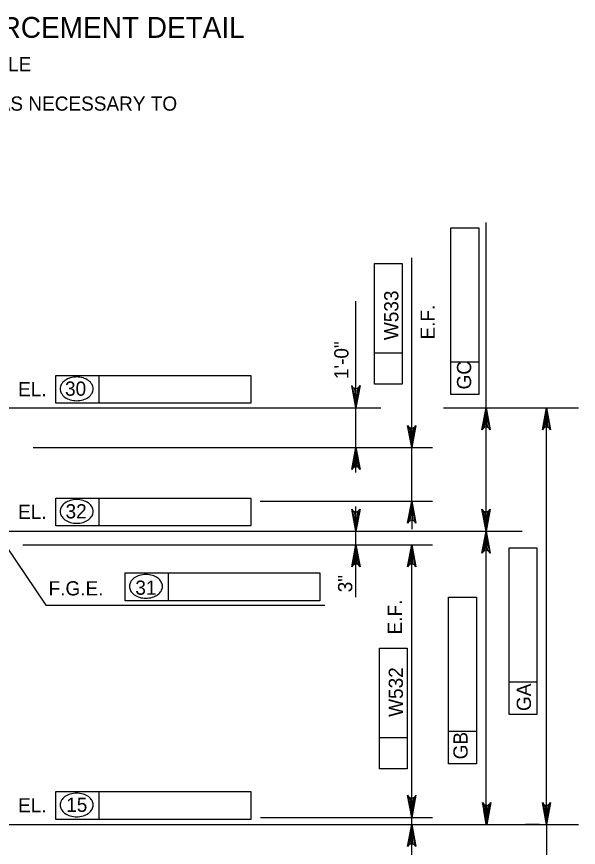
# Model space of a CAD drawing. Extents: x 638255 to 640306, y 296059 to 298435.
# Drawn here: x 638909 to 639027.7, y 296153 to 296328.5 of the extents above; entities that cross this region are included whole.
import ezdxf

# ---------------------------------------------------------------- set-up
doc = ezdxf.new("R2010")
doc.units = 0
doc.layers.add('Level 4', color=7, linetype='Continuous')

msp = doc.modelspace()

# ---------------------------------------------------------------- linework, layer by layer
at = {"layer": 'Level 4'}
for p, q in [((639000.74, 296248.66), (639000.74, 296283.9)), ((639000.74, 296283.9), (639006.63, 296283.9)), ((639006.63, 296283.9), (639006.63, 296248.66)), ((639008.19, 296222.73), (639008.19, 296285.04)), ((638992.48, 296248.08), (638992.48, 296277.54)), ((638984.61, 296250.82), (638984.61, 296276.31)), ((638984.61, 296276.31), (638990.5, 296276.31)), ((638990.5, 296276.31), (638990.5, 296250.82)), ((638980.7, 296232.2), (638980.7, 296268.36)), ((638990.5, 296257.4), (638984.61, 296257.4)), ((639006.63, 296255.5), (639000.74, 296255.5)), ((638917.35, 296252.7), (638958.48, 296252.7)), ((638917.35, 296246.8), (638917.35, 296252.7)), ((638926.5, 296246.8), (638926.5, 296252.7)), ((638958.48, 296252.7), (638958.48, 296246.8)), ((638990.5, 296250.82), (638984.61, 296250.82)), ((638992.48, 296240.42), (638992.48, 296248.08)), ((639006.63, 296248.66), (639000.74, 296248.66)), ((638835.01, 296245.87), (638985.96, 296245.87)), ((638958.48, 296246.8), (638917.35, 296246.8)), ((638999.22, 296245.87), (639027.68, 296245.87)), ((639005.73, 296245.87), (639012.61, 296245.87)), ((639014.63, 296245.87), (639025.37, 296245.87)), ((639020.95, 296157.77), (639020.95, 296245.87)), ((638912.53, 296237.48), (638996.9, 296237.48)), ((638992.48, 296226.13), (638992.48, 296237.48)), ((638917.35, 296226.78), (638958.48, 296226.78)), ((638917.35, 296220.89), (638917.35, 296226.78)), ((638926.5, 296220.89), (638926.5, 296226.78)), ((638958.48, 296226.78), (638958.48, 296220.89)), ((638960.49, 296226.13), (638996.9, 296226.13)), ((638980.7, 296205.86), (638980.7, 296224.96)), ((638992.48, 296223.18), (638992.48, 296220.23)), ((638958.48, 296220.89), (638917.35, 296220.89)), ((638906.78, 296219.78), (639015.83, 296219.78)), ((639002.85, 296219.78), (639012.61, 296219.78)), ((638906.76, 296216.71), (638915.21, 296204.13)), ((638910.35, 296216.92), (638996.9, 296216.92)), ((639008.19, 296160.72), (639008.19, 296216.83)), ((639013.05, 296181.05), (639013.05, 296216.29)), ((639013.05, 296216.29), (639018.94, 296216.29)), ((639018.94, 296216.29), (639018.94, 296181.05)), ((638992.48, 296147.95), (638992.48, 296213.97)), ((638931.98, 296205.06), (638931.98, 296210.96)), ((638931.98, 296210.96), (638973.11, 296210.96)), ((638941.13, 296205.06), (638941.13, 296210.96)), ((638973.11, 296210.96), (638973.11, 296205.06)), ((638973.11, 296205.06), (638931.98, 296205.06)), ((639000.28, 296170.58), (639000.28, 296205.82)), ((639000.28, 296205.82), (639006.18, 296205.82)), ((639006.18, 296205.82), (639006.18, 296170.58)), ((638915.21, 296204.13), (638974.12, 296204.13)), ((638985.66, 296169.55), (638985.66, 296195.04)), ((638985.66, 296195.04), (638991.55, 296195.04)), ((638991.55, 296195.04), (638991.55, 296169.55)), ((639018.94, 296187.89), (639013.05, 296187.89)), ((639018.94, 296181.05), (639013.05, 296181.05)), ((639006.18, 296177.42), (639000.28, 296177.42)), ((638991.55, 296176.13), (638985.66, 296176.13)), ((639006.18, 296170.58), (639000.28, 296170.58)), ((638991.55, 296169.55), (638985.66, 296169.55)), ((638917.35, 296164.76), (638958.48, 296164.76)), ((638917.35, 296158.87), (638917.35, 296164.76)), ((638926.5, 296158.87), (638926.5, 296164.76)), ((638958.48, 296164.76), (638958.48, 296158.87)), ((638960.55, 296159.3), (638996.9, 296159.3)), ((638906.62, 296157.77), (639027.68, 296157.77)), ((638958.48, 296158.87), (638917.35, 296158.87)), ((639002.85, 296157.77), (639012.61, 296157.77)), ((639014.63, 296157.77), (639025.37, 296157.77)), ((639019.48, 296157.77), (639016.53, 296157.77)), ((639020.95, 296157.77), (639020.95, 296145.49))]:
    msp.add_line(p, q, dxfattribs=at)
for points in [[(638980.7, 296245.87), (638979.82, 296250.53), (638980.07, 296250.17), (638980.38, 296249.98), (638980.7, 296249.93), (638981.01, 296249.98), (638981.32, 296250.17), (638981.57, 296250.53), (638980.7, 296245.87), (638981.32, 296250.17), (638981.01, 296249.98), (638980.7, 296245.87), (638980.7, 296249.93), (638980.38, 296249.98), (638980.7, 296245.87), (638980.07, 296250.17)], [(639008.19, 296245.87), (639009.06, 296241.22), (639008.81, 296241.58), (639008.5, 296241.77), (639008.19, 296241.82), (639007.87, 296241.77), (639007.56, 296241.58), (639007.31, 296241.22), (639008.19, 296245.87), (639007.56, 296241.58), (639007.87, 296241.77), (639008.19, 296245.87), (639008.19, 296241.82), (639008.5, 296241.77), (639008.19, 296245.87), (639008.81, 296241.58)], [(639020.95, 296245.87), (639021.82, 296241.22), (639021.57, 296241.58), (639021.26, 296241.77), (639020.95, 296241.82), (639020.63, 296241.77), (639020.32, 296241.58), (639020.07, 296241.22), (639020.95, 296245.87), (639020.32, 296241.58), (639020.63, 296241.77), (639020.95, 296245.87), (639020.95, 296241.82), (639021.26, 296241.77), (639020.95, 296245.87), (639021.57, 296241.58)], [(638992.48, 296237.48), (638991.61, 296242.13), (638991.86, 296241.77), (638992.17, 296241.59), (638992.48, 296241.53), (638992.8, 296241.59), (638993.11, 296241.77), (638993.36, 296242.13), (638992.48, 296237.48), (638993.11, 296241.77), (638992.8, 296241.59), (638992.48, 296237.48), (638992.48, 296241.53), (638992.17, 296241.59), (638992.48, 296237.48), (638991.86, 296241.77)], [(638980.7, 296237.48), (638981.57, 296232.83), (638981.32, 296233.18), (638981.01, 296233.37), (638980.7, 296233.42), (638980.38, 296233.37), (638980.07, 296233.18), (638979.82, 296232.83), (638980.7, 296237.48), (638980.07, 296233.18), (638980.38, 296233.37), (638980.7, 296237.48), (638980.7, 296233.42), (638981.01, 296233.37), (638980.7, 296237.48), (638981.32, 296233.18)], [(638992.48, 296226.13), (638993.36, 296221.48), (638993.11, 296221.83), (638992.8, 296222.02), (638992.48, 296222.07), (638992.17, 296222.02), (638991.86, 296221.83), (638991.61, 296221.48), (638992.48, 296226.13), (638991.86, 296221.83), (638992.17, 296222.02), (638992.48, 296226.13), (638992.48, 296222.07), (638992.8, 296222.02), (638992.48, 296226.13), (638993.11, 296221.83)], [(638980.7, 296219.78), (638979.82, 296224.43), (638980.07, 296224.07), (638980.38, 296223.89), (638980.7, 296223.84), (638981.01, 296223.89), (638981.32, 296224.07), (638981.57, 296224.43), (638980.7, 296219.78), (638981.32, 296224.07), (638981.01, 296223.89), (638980.7, 296219.78), (638980.7, 296223.84), (638980.38, 296223.89), (638980.7, 296219.78), (638980.07, 296224.07)], [(639008.19, 296219.78), (639007.31, 296224.43), (639007.56, 296224.07), (639007.87, 296223.89), (639008.19, 296223.84), (639008.5, 296223.89), (639008.81, 296224.07), (639009.06, 296224.43), (639008.19, 296219.78), (639008.81, 296224.07), (639008.5, 296223.89), (639008.19, 296219.78), (639008.19, 296223.84), (639007.87, 296223.89), (639008.19, 296219.78), (639007.56, 296224.07)], [(639008.19, 296219.78), (639009.06, 296215.13), (639008.81, 296215.49), (639008.5, 296215.67), (639008.19, 296215.73), (639007.87, 296215.67), (639007.56, 296215.49), (639007.31, 296215.13), (639008.19, 296219.78), (639007.56, 296215.49), (639007.87, 296215.67), (639008.19, 296219.78), (639008.19, 296215.73), (639008.5, 296215.67), (639008.19, 296219.78), (639008.81, 296215.49)], [(638980.7, 296216.92), (638981.57, 296212.27), (638981.32, 296212.63), (638981.01, 296212.81), (638980.7, 296212.86), (638980.38, 296212.81), (638980.07, 296212.63), (638979.82, 296212.27), (638980.7, 296216.92), (638980.07, 296212.63), (638980.38, 296212.81), (638980.7, 296216.92), (638980.7, 296212.86), (638981.01, 296212.81), (638980.7, 296216.92), (638981.32, 296212.63)], [(638992.48, 296216.92), (638993.36, 296212.27), (638993.11, 296212.63), (638992.8, 296212.81), (638992.48, 296212.86), (638992.17, 296212.81), (638991.86, 296212.63), (638991.61, 296212.27), (638992.48, 296216.92), (638991.86, 296212.63), (638992.17, 296212.81), (638992.48, 296216.92), (638992.48, 296212.86), (638992.8, 296212.81), (638992.48, 296216.92), (638993.11, 296212.63)], [(638992.48, 296159.3), (638991.61, 296163.96), (638991.86, 296163.6), (638992.17, 296163.41), (638992.48, 296163.36), (638992.8, 296163.41), (638993.11, 296163.6), (638993.36, 296163.96), (638992.48, 296159.3), (638993.11, 296163.6), (638992.8, 296163.41), (638992.48, 296159.3), (638992.48, 296163.36), (638992.17, 296163.41), (638992.48, 296159.3), (638991.86, 296163.6)], [(639008.33, 296157.77), (639007.46, 296162.42), (639007.71, 296162.06), (639008.02, 296161.88), (639008.33, 296161.82), (639008.64, 296161.88), (639008.96, 296162.06), (639009.2, 296162.42), (639008.33, 296157.77), (639008.96, 296162.06), (639008.64, 296161.88), (639008.33, 296157.77), (639008.33, 296161.82), (639008.02, 296161.88), (639008.33, 296157.77), (639007.71, 296162.06)], [(639020.95, 296157.77), (639020.07, 296162.42), (639020.32, 296162.06), (639020.63, 296161.88), (639020.95, 296161.82), (639021.26, 296161.88), (639021.57, 296162.06), (639021.82, 296162.42), (639020.95, 296157.77), (639021.57, 296162.06), (639021.26, 296161.88), (639020.95, 296157.77), (639020.95, 296161.82), (639020.63, 296161.88), (639020.95, 296157.77), (639020.32, 296162.06)], [(638992.48, 296157.77), (638993.36, 296153.12), (638993.11, 296153.47), (638992.8, 296153.66), (638992.48, 296153.71), (638992.17, 296153.66), (638991.86, 296153.47), (638991.61, 296153.12), (638992.48, 296157.77), (638991.86, 296153.47), (638992.17, 296153.66), (638992.48, 296157.77), (638992.48, 296153.71), (638992.8, 296153.66), (638992.48, 296157.77), (638993.11, 296153.47)]]:
    msp.add_lwpolyline(points, dxfattribs=at)
for points in [[(639007.69, 296242.93), (639008.68, 296242.93), (639008.19, 296245.87)], [(639020.46, 296242.93), (639021.44, 296242.93), (639020.95, 296245.87)], [(638991.99, 296240.42), (638992.97, 296240.42), (638992.48, 296237.48)], [(638980.21, 296234.53), (638981.19, 296234.53), (638980.7, 296237.48)], [(638991.99, 296223.18), (638992.97, 296223.18), (638992.48, 296226.13)], [(638980.21, 296222.73), (638981.19, 296222.73), (638980.7, 296219.78)], [(639007.69, 296222.73), (639008.68, 296222.73), (639008.19, 296219.78)], [(639007.69, 296216.83), (639008.68, 296216.83), (639008.19, 296219.78)], [(638980.21, 296213.97), (638981.19, 296213.97), (638980.7, 296216.92)], [(638991.99, 296213.97), (638992.97, 296213.97), (638992.48, 296216.92)], [(638991.99, 296162.25), (638992.97, 296162.25), (638992.48, 296159.3)], [(639007.69, 296160.72), (639008.68, 296160.72), (639008.19, 296157.77)], [(639020.46, 296160.72), (639021.44, 296160.72), (639020.95, 296157.77)], [(638991.99, 296154.82), (638992.97, 296154.82), (638992.48, 296157.77)]]:
    msp.add_lwpolyline(points, close=True, dxfattribs=at)
for centre, radius, start, end in [((638921.72, 296247.5), 4.86, 90, 106.5358), ((638921.72, 296247.5), 4.86, 73.4642, 90), ((638920.05, 296249.86), 1.82, 149.9767, 180), ((638920.85, 296249.39), 2.75, 125.6316, 149.9767), ((638921.38, 296248.66), 3.65, 106.5358, 125.6316), ((638922.06, 296248.66), 3.65, 54.3684, 73.4642), ((638922.59, 296249.39), 2.75, 30.0233, 54.3684), ((638923.39, 296249.86), 1.82, 0, 30.0233), ((638920.05, 296249.86), 1.82, 180, 210.0233), ((638920.85, 296250.32), 2.75, 210.0233, 234.3684), ((638922.59, 296250.32), 2.75, 305.6316, 329.9767), ((638923.39, 296249.86), 1.82, 329.9767, 0), ((638921.38, 296251.05), 3.65, 234.3684, 253.4642), ((638921.72, 296252.21), 4.86, 253.4642, 270), ((638921.72, 296252.21), 4.86, 270, 286.5358), ((638922.06, 296251.05), 3.65, 286.5358, 305.6316), ((638921.38, 296222.75), 3.65, 106.5358, 125.6316), ((638921.72, 296221.59), 4.86, 90, 106.5358), ((638921.72, 296221.59), 4.86, 73.4642, 90), ((638922.06, 296222.75), 3.65, 54.3684, 73.4642), ((638920.05, 296223.94), 1.82, 149.9767, 180), ((638920.85, 296223.48), 2.75, 125.6316, 149.9767), ((638922.59, 296223.48), 2.75, 30.0233, 54.3684), ((638923.39, 296223.94), 1.82, 0, 30.0233), ((638920.05, 296223.94), 1.82, 180, 210.0233), ((638920.85, 296224.41), 2.75, 210.0233, 234.3684), ((638922.59, 296224.41), 2.75, 305.6316, 329.9767), ((638923.39, 296223.94), 1.82, 329.9767, 0), ((638921.38, 296225.14), 3.65, 234.3684, 253.4642), ((638921.72, 296226.3), 4.86, 253.4642, 270), ((638921.72, 296226.3), 4.86, 270, 286.5358), ((638922.06, 296225.14), 3.65, 286.5358, 305.6316), ((638936.01, 296206.92), 3.65, 106.5358, 125.6316), ((638936.35, 296205.76), 4.86, 90, 106.5358), ((638936.35, 296205.76), 4.86, 73.4642, 90), ((638936.69, 296206.92), 3.65, 54.3684, 73.4642), ((638934.68, 296208.12), 1.82, 149.9767, 180), ((638935.48, 296207.65), 2.75, 125.6316, 149.9767), ((638937.22, 296207.65), 2.75, 30.0233, 54.3684), ((638938.02, 296208.12), 1.82, 0, 30.0233), ((638934.68, 296208.12), 1.82, 180, 210.0233), ((638935.48, 296208.58), 2.75, 210.0233, 234.3684), ((638937.22, 296208.58), 2.75, 305.6316, 329.9767), ((638938.02, 296208.12), 1.82, 329.9767, 0), ((638936.01, 296209.31), 3.65, 234.3684, 253.4642), ((638936.35, 296210.47), 4.86, 253.4642, 270), ((638936.35, 296210.47), 4.86, 270, 286.5358), ((638936.69, 296209.31), 3.65, 286.5358, 305.6316), ((638920.05, 296161.92), 1.82, 149.9767, 180), ((638920.85, 296161.46), 2.75, 125.6316, 149.9767), ((638921.38, 296160.72), 3.65, 106.5358, 125.6316), ((638921.72, 296159.56), 4.86, 90, 106.5358), ((638921.72, 296159.56), 4.86, 73.4642, 90), ((638922.06, 296160.72), 3.65, 54.3684, 73.4642), ((638922.59, 296161.46), 2.75, 30.0233, 54.3684), ((638923.39, 296161.92), 1.82, 0, 30.0233), ((638920.05, 296161.92), 1.82, 180, 210.0233), ((638920.85, 296162.38), 2.75, 210.0233, 234.3684), ((638922.59, 296162.38), 2.75, 305.6316, 329.9767), ((638923.39, 296161.92), 1.82, 329.9767, 0), ((638921.38, 296163.12), 3.65, 234.3684, 253.4642), ((638921.72, 296164.28), 4.86, 253.4642, 270), ((638921.72, 296164.28), 4.86, 270, 286.5358), ((638922.06, 296163.12), 3.65, 286.5358, 305.6316)]:
    msp.add_arc(centre, radius, start, end, dxfattribs=at)

# ---------------------------------------------------------------- texts
for s, height, p in [('WEEPHOLE REINFORCEMENT DETAIL', 4.4207, (638848.17, 296324.03)), ('NO SCALE', 3, (638891.85, 296316.95)), ('ADJUST REINFORCEMENT AS NECESSARY TO', 3.0001, (638852.22, 296308.64)), ('EL.', 3, (638909.35, 296248.28)), ('30', 3, (638919.26, 296248.4)), ('EL.', 3, (638909.35, 296222.37)), ('32', 3, (638919.37, 296222.48)), ('F.G.E.', 3, (638915.79, 296206.2)), ('31', 3, (638934.11, 296206.34)), ('EL.', 3, (638909.35, 296160.35)), ('15', 3, (638919.51, 296160.46))]:
    msp.add_text(s, height=height, dxfattribs=at).set_placement(p)
for s, p in [('W533', (638989.66, 296260.15)), ('E.F.', (638997.35, 296260.29)), ('1\'-0"', (638979.12, 296251.91)), ('GC', (639005.04, 296249.72)), ('3"', (638979.92, 296206.86)), ('E.F.', (638990.42, 296197.96)), ('W532', (638990.62, 296180.54)), ('GA', (639017.66, 296181.77)), ('GB', (639004.29, 296171.56))]:
    msp.add_text(s, height=3, rotation=90, dxfattribs=at).set_placement(p)

doc.saveas('drawing.dxf')
